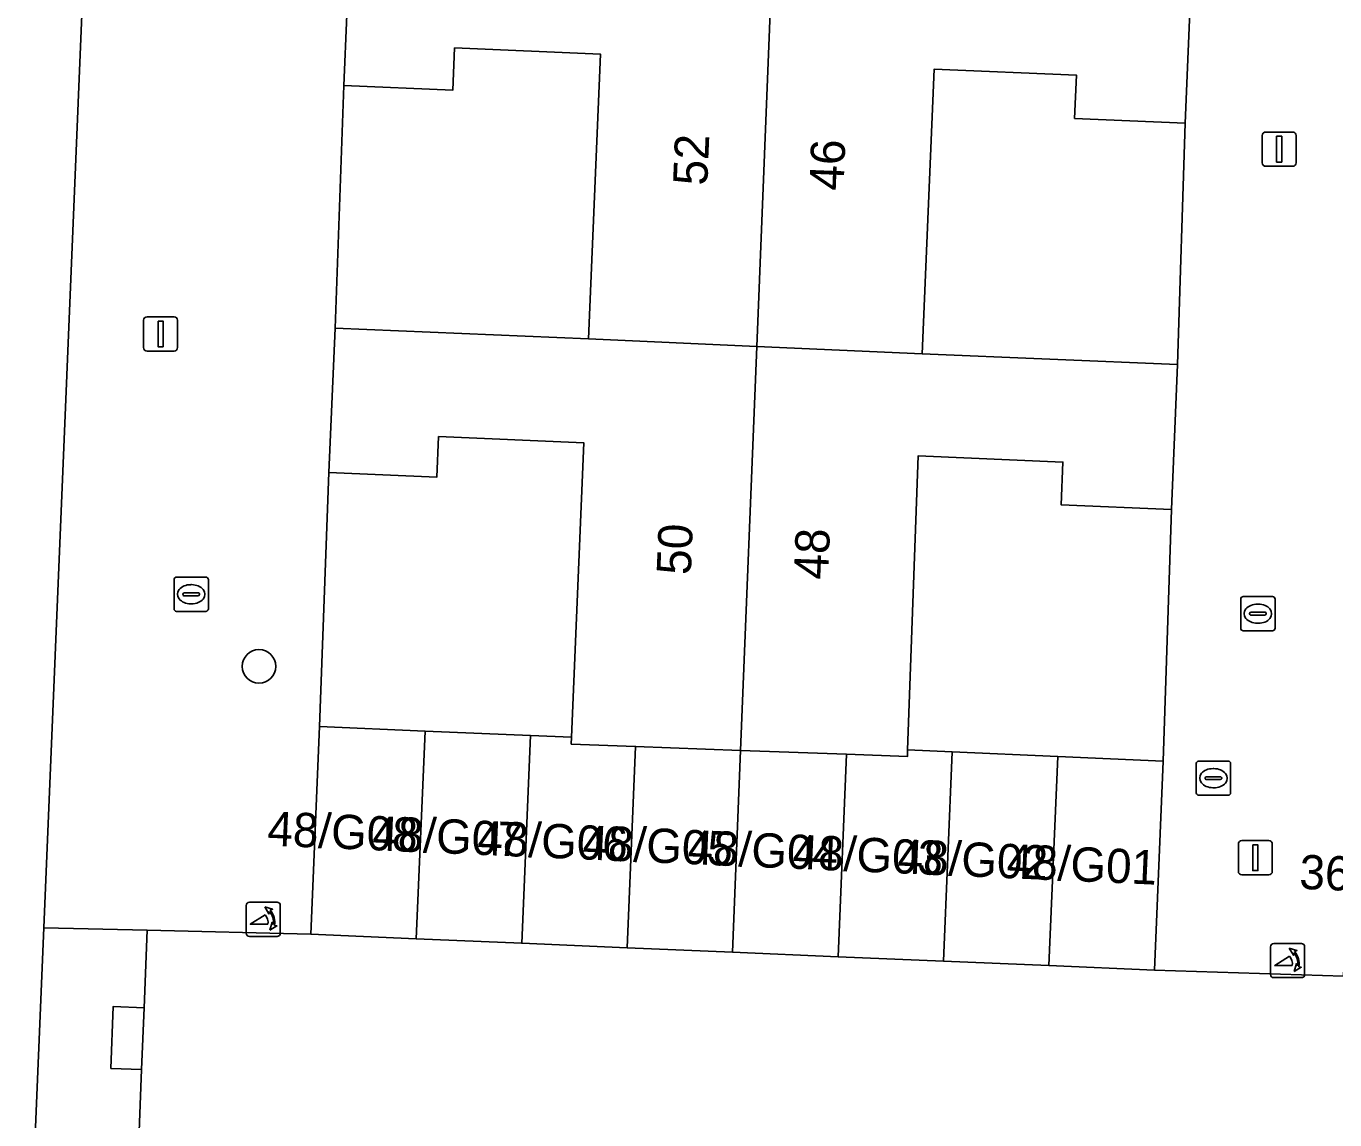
# Model space of a CAD drawing. Extents: x 160786 to 161429, y 386828 to 387485.
# Drawn here: x 161166.3 to 161204.51, y 387331.11 to 387363.03 of the extents above; entities that cross this region are included whole.
import ezdxf

# ---------------------------------------------------------------- set-up
doc = ezdxf.new("R2010")
doc.units = 0
for name, color, linetype in [('IMGEO_Boom', 7, 'Continuous'), ('IMGEO_Brandkraan', 7, 'Continuous'), ('IMGEO_Erf', 7, 'Continuous'), ('IMGEO_Groenvoorziening', 7, 'Continuous'), ('IMGEO_Kolk', 7, 'Continuous'), ('IMGEO_Lichtmast', 7, 'Continuous'), ('IMGEO_Muur', 7, 'Continuous'), ('IMGEO_Pand', 7, 'Continuous'), ('IMGEO_Pand_nummerreeks', 7, 'Continuous'), ('IMGEO_Poller', 7, 'Continuous'), ('IMGEO_Rijbaan_lokaal_open', 7, 'Continuous'), ('IMGEO_Voetpad_open', 7, 'Continuous')]:
    doc.layers.add(name, color=color, linetype=linetype)

msp = doc.modelspace()

# ---------------------------------------------------------------- linework, layer by layer
at = {"layer": 'IMGEO_Boom'}
msp.add_circle((161173.099, 387344.343), 0.489, dxfattribs=at)
at = {"layer": 'IMGEO_Brandkraan'}
for p, q in [((161200.463, 387340.654), (161200.463, 387341.506)), ((161200.538, 387341.58), (161201.39, 387341.58)), ((161201.464, 387341.506), (161201.464, 387340.654)), ((161200.765, 387341.123), (161201.163, 387341.123)), ((161200.951, 387341.36), (161200.976, 387341.36)), ((161200.722, 387341.074), (161200.722, 387341.086)), ((161201.16, 387341.037), (161200.762, 387341.037)), ((161200.974, 387340.8), (161200.949, 387340.8)), ((161201.206, 387341.086), (161201.206, 387341.074)), ((161201.39, 387340.58), (161200.538, 387340.58))]:
    msp.add_line(p, q, dxfattribs=at)
for points in [[(161200.463, 387340.654), (161200.463, 387341.506)], [(161200.538, 387341.58), (161201.39, 387341.58)], [(161201.464, 387341.506), (161201.464, 387340.654)], [(161201.39, 387340.58), (161200.538, 387340.58)]]:
    msp.add_lwpolyline(points, dxfattribs=at)
for centre, radius, start, end in [((161200.54, 387341.504), 0.0765, 91.552, 178.448), ((161200.54, 387341.504), 0.0765, 91.552, 178.448), ((161201.388, 387341.504), 0.0765, 1.552, 88.448), ((161201.388, 387341.504), 0.0765, 1.552, 88.448), ((161200.762, 387341.083), 0.0403, 85.8775, 175.7526), ((161201.167, 387341.085), 0.0386, 1.7309, 96.639), ((161200.759, 387341.073), 0.0366, 178.938, 274.7102), ((161201.163, 387341.08), 0.043, 264.8664, 352.4533), ((161200.54, 387340.656), 0.0765, 181.552, 268.448), ((161200.54, 387340.656), 0.0765, 181.552, 268.448), ((161201.388, 387340.656), 0.0765, 271.552, 358.448), ((161201.388, 387340.656), 0.0765, 271.552, 358.448)]:
    msp.add_arc(centre, radius, start, end, dxfattribs=at)
for centre, major_axis, ratio, start_param, end_param in [((161200.95, 387341.08), (-0.387, 0.002), 0.722429, 4.712389, 7.853982), ((161200.975, 387341.08), (-0.39, 0.002), 0.717154, 1.570796, 4.712389)]:
    msp.add_ellipse(centre, major_axis=major_axis, ratio=ratio, start_param=start_param, end_param=end_param, dxfattribs=at)
at = {"layer": 'IMGEO_Erf'}
msp.add_lwpolyline([(161165.215, 387298.514), (161166.813, 387336.716), (161168.496, 387376.93), (161166.008, 387377.063)], dxfattribs=at)
for points in [[(161175.318, 387354.218), (161182.714, 387353.905), (161183.066, 387362.214), (161178.811, 387362.394), (161178.759, 387361.164), (161175.573, 387361.299)], [(161200.134, 387360.197), (161196.91, 387360.333), (161196.963, 387361.599), (161192.814, 387361.775), (161192.462, 387353.466), (161199.917, 387353.15)], [(161174.868, 387342.585), (161177.946, 387342.455), (161181.025, 387342.325), (161182.22, 387342.274), (161182.578, 387350.869), (161178.343, 387351.048), (161178.293, 387349.869), (161175.139, 387350.002)], [(161199.737, 387348.918), (161196.518, 387349.054), (161196.571, 387350.307), (161192.341, 387350.486), (161192.035, 387341.909), (161193.34, 387341.851), (161196.418, 387341.716), (161199.497, 387341.58)]]:
    msp.add_lwpolyline(points, close=True, dxfattribs=at)
at = {"layer": 'IMGEO_Groenvoorziening'}
msp.add_lwpolyline([(161169.672, 387332.573), (161169.743, 387334.382), (161168.845, 387334.418), (161168.774, 387332.609)], close=True, dxfattribs=at)
at = {"layer": 'IMGEO_Kolk'}
for p, q in [((161170.619, 387346.022), (161170.619, 387346.874)), ((161170.694, 387346.948), (161171.546, 387346.948)), ((161171.62, 387346.874), (161171.62, 387346.022)), ((161170.878, 387346.442), (161170.878, 387346.454)), ((161170.921, 387346.491), (161171.319, 387346.491)), ((161171.107, 387346.728), (161171.132, 387346.728)), ((161171.362, 387346.454), (161171.362, 387346.442)), ((161171.316, 387346.405), (161170.918, 387346.405)), ((161171.13, 387346.168), (161171.105, 387346.168)), ((161201.761, 387345.454), (161201.761, 387346.306)), ((161201.836, 387346.38), (161202.688, 387346.38)), ((161202.249, 387346.16), (161202.274, 387346.16)), ((161202.762, 387346.306), (161202.762, 387345.454)), ((161171.546, 387345.948), (161170.694, 387345.948)), ((161202.02, 387345.874), (161202.02, 387345.886)), ((161202.458, 387345.837), (161202.06, 387345.837)), ((161202.063, 387345.923), (161202.461, 387345.923)), ((161202.504, 387345.886), (161202.504, 387345.874)), ((161202.688, 387345.38), (161201.836, 387345.38)), ((161202.272, 387345.6), (161202.247, 387345.6))]:
    msp.add_line(p, q, dxfattribs=at)
for points in [[(161170.619, 387346.022), (161170.619, 387346.874)], [(161170.694, 387346.948), (161171.546, 387346.948)], [(161171.62, 387346.874), (161171.62, 387346.022)], [(161201.761, 387345.454), (161201.761, 387346.306)], [(161201.836, 387346.38), (161202.688, 387346.38)], [(161202.762, 387346.306), (161202.762, 387345.454)], [(161171.546, 387345.948), (161170.694, 387345.948)], [(161202.688, 387345.38), (161201.836, 387345.38)]]:
    msp.add_lwpolyline(points, dxfattribs=at)
for centre, radius, start, end in [((161170.696, 387346.872), 0.0765, 91.552, 178.448), ((161170.696, 387346.872), 0.0765, 91.552, 178.448), ((161171.544, 387346.872), 0.0765, 1.552, 88.448), ((161171.544, 387346.872), 0.0765, 1.552, 88.448), ((161170.918, 387346.451), 0.0403, 85.8775, 175.7526), ((161171.323, 387346.453), 0.0386, 1.7309, 96.639), ((161170.915, 387346.441), 0.0366, 178.938, 274.7102), ((161171.319, 387346.448), 0.043, 264.8664, 352.4533), ((161201.838, 387346.304), 0.0765, 91.552, 178.448), ((161201.838, 387346.304), 0.0765, 91.552, 178.448), ((161202.686, 387346.304), 0.0765, 1.552, 88.448), ((161202.686, 387346.304), 0.0765, 1.552, 88.448), ((161170.696, 387346.024), 0.0765, 181.552, 268.448), ((161170.696, 387346.024), 0.0765, 181.552, 268.448), ((161171.544, 387346.024), 0.0765, 271.552, 358.448), ((161171.544, 387346.024), 0.0765, 271.552, 358.448), ((161202.06, 387345.883), 0.0403, 85.8775, 175.7526), ((161202.057, 387345.873), 0.0366, 178.938, 274.7102), ((161202.461, 387345.88), 0.043, 264.8664, 352.4533), ((161202.465, 387345.885), 0.0386, 1.7309, 96.639), ((161201.838, 387345.456), 0.0765, 181.552, 268.448), ((161201.838, 387345.456), 0.0765, 181.552, 268.448), ((161202.686, 387345.456), 0.0765, 271.552, 358.448), ((161202.686, 387345.456), 0.0765, 271.552, 358.448)]:
    msp.add_arc(centre, radius, start, end, dxfattribs=at)
for centre, major_axis, ratio, start_param, end_param in [((161171.106, 387346.448), (-0.387, 0.002), 0.722429, 4.712389, 7.853982), ((161171.131, 387346.448), (-0.39, 0.002), 0.717154, 1.570796, 4.712389), ((161202.248, 387345.88), (-0.387, 0.002), 0.722429, 4.712389, 7.853982), ((161202.273, 387345.88), (-0.39, 0.002), 0.717154, 1.570796, 4.712389)]:
    msp.add_ellipse(centre, major_axis=major_axis, ratio=ratio, start_param=start_param, end_param=end_param, dxfattribs=at)
at = {"layer": 'IMGEO_Lichtmast'}
for p, q in [((161202.389, 387359.038), (161202.389, 387359.838)), ((161202.389, 387359.838), (161202.389, 387359.038)), ((161202.489, 387359.938), (161203.279, 387359.938)), ((161203.279, 387359.938), (161202.489, 387359.938)), ((161203.379, 387359.838), (161203.379, 387359.038)), ((161203.379, 387359.038), (161203.379, 387359.838)), ((161203.279, 387358.938), (161202.489, 387358.938)), ((161202.489, 387358.938), (161203.279, 387358.938)), ((161169.831, 387354.546), (161170.621, 387354.546)), ((161170.621, 387354.546), (161169.831, 387354.546)), ((161169.731, 387353.646), (161169.731, 387354.446)), ((161169.731, 387354.446), (161169.731, 387353.646)), ((161170.721, 387354.446), (161170.721, 387353.646)), ((161170.721, 387353.646), (161170.721, 387354.446)), ((161170.621, 387353.546), (161169.831, 387353.546)), ((161169.831, 387353.546), (161170.621, 387353.546)), ((161201.791, 387339.257), (161202.581, 387339.257)), ((161202.581, 387339.257), (161201.791, 387339.257)), ((161201.691, 387338.357), (161201.691, 387339.157)), ((161201.691, 387339.157), (161201.691, 387338.357)), ((161202.681, 387339.157), (161202.681, 387338.357)), ((161202.681, 387338.357), (161202.681, 387339.157)), ((161202.581, 387338.257), (161201.791, 387338.257)), ((161201.791, 387338.257), (161202.581, 387338.257))]:
    msp.add_line(p, q, dxfattribs=at)
for points in [[(161202.809, 387359.813), (161202.959, 387359.813), (161202.959, 387359.063), (161202.809, 387359.063), (161202.809, 387359.813)], [(161170.151, 387354.421), (161170.301, 387354.421), (161170.301, 387353.671), (161170.151, 387353.671), (161170.151, 387354.421)], [(161202.111, 387339.132), (161202.261, 387339.132), (161202.261, 387338.382), (161202.111, 387338.382), (161202.111, 387339.132)]]:
    msp.add_lwpolyline(points, dxfattribs=at)
for centre, start, end in [((161202.489, 387359.838), 90, 180), ((161202.489, 387359.838), 90, 180), ((161203.279, 387359.838), 0, 90), ((161203.279, 387359.838), 360, 90), ((161202.489, 387359.038), 180, 270), ((161202.489, 387359.038), 180, 270), ((161203.279, 387359.038), 270, 0), ((161203.279, 387359.038), 270, 0), ((161169.831, 387354.446), 90, 180), ((161169.831, 387354.446), 90, 180), ((161170.621, 387354.446), 0, 90), ((161170.621, 387354.446), 360, 90), ((161169.831, 387353.646), 180, 270), ((161169.831, 387353.646), 180, 270), ((161170.621, 387353.646), 270, 0), ((161170.621, 387353.646), 270, 0), ((161201.791, 387339.157), 90, 180), ((161201.791, 387339.157), 90, 180), ((161202.581, 387339.157), 0, 90), ((161202.581, 387339.157), 360, 90), ((161201.791, 387338.357), 180, 270), ((161201.791, 387338.357), 180, 270), ((161202.581, 387338.357), 270, 0), ((161202.581, 387338.357), 270, 0)]:
    msp.add_arc(centre, 0.1, start, end, dxfattribs=at)
at = {"layer": 'IMGEO_Muur'}
for points in [[(161175.573, 387361.299), (161175.318, 387354.218)], [(161199.917, 387353.15), (161200.134, 387360.197)], [(161175.139, 387350.002), (161174.868, 387342.585)], [(161199.497, 387341.58), (161199.737, 387348.918)]]:
    msp.add_lwpolyline(points, dxfattribs=at)
at = {"layer": 'IMGEO_Pand'}
for points in [[(161175.573, 387361.299), (161178.759, 387361.164), (161178.811, 387362.394), (161183.066, 387362.214), (161182.714, 387353.905), (161187.629, 387353.683), (161188.076, 387364.906), (161183.184, 387365.114), (161175.748, 387365.429)], [(161200.311, 387364.387), (161194.454, 387364.635), (161192.911, 387364.7), (161188.076, 387364.906), (161187.629, 387353.683), (161192.462, 387353.466), (161192.814, 387361.775), (161196.963, 387361.599), (161196.91, 387360.333), (161200.134, 387360.197)], [(161187.16, 387341.892), (161187.629, 387353.683), (161182.714, 387353.905), (161175.318, 387354.218), (161175.139, 387350.002), (161178.293, 387349.869), (161178.343, 387351.048), (161182.578, 387350.869), (161182.22, 387342.274), (161182.213, 387342.076), (161184.095, 387342.006)], [(161199.917, 387353.15), (161192.462, 387353.466), (161187.629, 387353.683), (161187.16, 387341.892), (161190.253, 387341.777), (161192.028, 387341.711), (161192.035, 387341.909), (161192.341, 387350.486), (161196.571, 387350.307), (161196.518, 387349.054), (161199.737, 387348.918)], [(161174.611, 387336.523), (161177.689, 387336.392), (161177.946, 387342.455), (161174.868, 387342.585)], [(161181.025, 387342.325), (161177.946, 387342.455), (161177.689, 387336.392), (161180.768, 387336.262)], [(161182.213, 387342.076), (161182.22, 387342.274), (161181.025, 387342.325), (161180.768, 387336.262), (161183.846, 387336.131), (161184.095, 387342.006)], [(161184.095, 387342.006), (161183.846, 387336.131), (161186.924, 387336.001), (161187.16, 387341.892)], [(161186.924, 387336.001), (161190.003, 387335.87), (161190.253, 387341.777), (161187.16, 387341.892)], [(161193.34, 387341.851), (161192.035, 387341.909), (161192.028, 387341.711), (161190.253, 387341.777), (161190.003, 387335.87), (161193.081, 387335.74)], [(161193.081, 387335.74), (161196.16, 387335.609), (161196.418, 387341.716), (161193.34, 387341.851)], [(161199.238, 387335.479), (161199.497, 387341.58), (161196.418, 387341.716), (161196.16, 387335.609)]]:
    msp.add_lwpolyline(points, close=True, dxfattribs=at)
at = {"layer": 'IMGEO_Poller'}
for p, q in [((161172.724, 387337.365), (161172.724, 387336.558)), ((161172.724, 387337.365), (161172.724, 387336.558)), ((161173.626, 387337.46), (161172.818, 387337.46)), ((161173.626, 387337.46), (161172.818, 387337.46)), ((161173.72, 387336.558), (161173.72, 387337.365)), ((161173.72, 387336.558), (161173.72, 387337.365)), ((161172.818, 387336.463), (161173.626, 387336.463)), ((161172.818, 387336.463), (161173.626, 387336.463)), ((161202.629, 387336.16), (161202.629, 387335.353)), ((161202.629, 387336.16), (161202.629, 387335.353)), ((161203.531, 387336.255), (161202.723, 387336.255)), ((161203.531, 387336.255), (161202.723, 387336.255)), ((161203.625, 387335.353), (161203.625, 387336.16)), ((161203.625, 387335.353), (161203.625, 387336.16)), ((161202.723, 387335.258), (161203.531, 387335.258)), ((161202.723, 387335.258), (161203.531, 387335.258))]:
    msp.add_line(p, q, dxfattribs=at)
for points in [[(161173.403, 387337.189), (161173.391, 387337.116), (161173.266, 387337.321)], [(161173.266, 387337.321), (161173.497, 387337.255), (161173.426, 387337.223)], [(161173.359, 387336.816), (161172.846, 387336.816), (161173.276, 387337.091)], [(161173.419, 387336.644), (161173.485, 387336.875), (161173.515, 387336.807)], [(161173.551, 387336.78), (161173.623, 387336.769), (161173.419, 387336.644)], [(161203.264, 387335.611), (161202.751, 387335.611), (161203.181, 387335.886)], [(161203.308, 387335.984), (161203.296, 387335.911), (161203.171, 387336.116)], [(161203.171, 387336.116), (161203.402, 387336.05), (161203.331, 387336.018)], [(161203.324, 387335.439), (161203.39, 387335.67), (161203.42, 387335.602)], [(161203.456, 387335.575), (161203.528, 387335.564), (161203.324, 387335.439)]]:
    msp.add_lwpolyline(points, dxfattribs=at)
for centre, radius, start, end in [((161172.818, 387337.365), 0.0946, 90, 180), ((161172.818, 387337.365), 0.0946, 90, 180), ((161173.626, 387337.365), 0.0946, 0, 90), ((161173.626, 387337.365), 0.0946, 0, 90), ((161173.031, 387336.866), 0.332, 351.3247, 42.4854), ((161173.045, 387336.876), 0.476, 351.7527, 41.1691), ((161173.045, 387336.876), 0.516, 349.3569, 42.2912), ((161172.818, 387336.558), 0.0946, 180, 270), ((161172.818, 387336.558), 0.0946, 180, 270), ((161173.626, 387336.558), 0.0946, 270, 0), ((161173.626, 387336.558), 0.0946, 270, 0), ((161202.723, 387336.16), 0.0946, 90, 180), ((161202.723, 387336.16), 0.0946, 90, 180), ((161203.531, 387336.16), 0.0946, 0, 90), ((161203.531, 387336.16), 0.0946, 0, 90), ((161202.936, 387335.661), 0.332, 351.3247, 42.4854), ((161202.95, 387335.671), 0.476, 351.7527, 41.1691), ((161202.95, 387335.671), 0.516, 349.3569, 42.2912), ((161202.723, 387335.353), 0.0946, 180, 270), ((161202.723, 387335.353), 0.0946, 180, 270), ((161203.531, 387335.353), 0.0946, 270, 0), ((161203.531, 387335.353), 0.0946, 270, 0)]:
    msp.add_arc(centre, radius, start, end, dxfattribs=at)
at = {"layer": 'IMGEO_Rijbaan_lokaal_open'}
msp.add_lwpolyline([(161204.762, 387335.298), (161199.238, 387335.479), (161196.16, 387335.609), (161193.081, 387335.74), (161190.003, 387335.87), (161186.924, 387336.001), (161183.846, 387336.131), (161180.768, 387336.262), (161177.689, 387336.392), (161174.611, 387336.523), (161169.832, 387336.641), (161169.743, 387334.382), (161169.672, 387332.573), (161169.53, 387328.966)], dxfattribs=at)
at = {"layer": 'IMGEO_Voetpad_open'}
for points in [[(161175.573, 387361.299), (161175.748, 387365.429), (161176.066, 387372.577), (161176.241, 387376.703), (161168.496, 387376.93), (161166.813, 387336.716), (161169.832, 387336.641), (161174.611, 387336.523), (161174.868, 387342.585), (161175.139, 387350.002), (161175.318, 387354.218)], [(161205.72, 387360.028), (161205.89, 387364.23), (161205.994, 387367.533), (161206.113, 387371.322), (161206.28, 387375.428), (161200.81, 387375.661), (161200.635, 387371.531), (161200.311, 387364.387), (161200.134, 387360.197), (161199.917, 387353.15), (161199.737, 387348.918), (161199.497, 387341.58), (161199.238, 387335.479), (161204.762, 387335.298), (161205.008, 387341.37), (161205.256, 387348.838), (161205.422, 387352.929)]]:
    msp.add_lwpolyline(points, close=True, dxfattribs=at)
msp.add_lwpolyline([(161168.933, 387313.767), (161169.022, 387316.036), (161168.124, 387316.072), (161168.195, 387317.88), (161169.093, 387317.844), (161169.235, 387321.452), (161168.337, 387321.488), (161168.419, 387323.586), (161169.317, 387323.55), (161169.459, 387327.157), (161168.561, 387327.193), (161168.632, 387329.002), (161169.53, 387328.966), (161169.672, 387332.573), (161168.774, 387332.609), (161168.845, 387334.418), (161169.743, 387334.382), (161169.832, 387336.641), (161166.813, 387336.716), (161165.215, 387298.514), (161165.127, 387296.415), (161164.993, 387293.208), (161164.829, 387289.6), (161170.163, 387289.466)], dxfattribs=at)

# ---------------------------------------------------------------- texts
at = {"layer": 'IMGEO_Pand_nummerreeks'}
for s, rotation, p in [('52', 87.5811, (161186.184, 387358.365)), ('46', 87.7256, (161190.162, 387358.217)), ('50', 87.5811, (161185.704, 387346.999)), ('48', 87.7229, (161189.71, 387346.865)), ('48/G08', 357.4748, (161173.329, 387339.116)), ('48/G07', 357.4748, (161176.394, 387338.981)), ('48/G06', 357.4748, (161179.462, 387338.846)), ('48/G05', 357.4748, (161182.53, 387338.711)), ('48/G04', 357.4748, (161185.598, 387338.575)), ('48/G03', 357.4748, (161188.666, 387338.44)), ('48/G02', 357.4748, (161191.728, 387338.305)), ('48/G01', 357.4748, (161194.913, 387338.164)), ('36/G08', 357.7224, (161203.459, 387337.85))]:
    msp.add_text(s, height=1, rotation=rotation, dxfattribs=at).set_placement(p)

doc.saveas('drawing.dxf')
